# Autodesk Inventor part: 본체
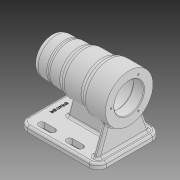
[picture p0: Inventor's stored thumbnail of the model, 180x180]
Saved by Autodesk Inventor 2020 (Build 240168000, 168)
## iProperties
Created: 2021-10
Part Number: 본체
Material: 일반
Document SubType Name: Modeling
Designer: user
Density: 1 g/cm^3
Appearance: 기본값
Author: user
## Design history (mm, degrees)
sketch "스케치1"
  geometry: L1 (56, 4)-(56, 17); L2 (56, 17)-(24, 17); L3 (24, 17)-(24, 13); L4 (24, 13)-(-10, 13); L5 (-10, 13)-(-10, 10); L6 (-10, 10)-(-32, 10); L7 (-32, 10)-(-32, 9); L8 (-32, 9)-(-56, 9); L9 (-56, 9)-(-56, -17); L10 (41, 4)-(56, 4); L11 (41, 4)-(41, 4); L12 (38, 7)-(-10, 7); L13 (-13, 4)-(-24.7, 4); L14 (-42.7, 0.5)-(-25, 0.5); L15 (-46.7, -1)-(-43, -1); L16 (-50, -17)-(-50, -9.5); L17 (-47, -6.5)-(-47, -6.5); L18 (-47, -1.3)-(-47, -6.5); L19 (-43, -1)-(-43, 0.2); L20 (-25, 0.5)-(-25, 3.7); L21 (-13, 4)-(-13, 4); L22 (-56, -17)-(41, -17); L23 (41, -17)-(41, 4); A1 r 3 centre (38, 4) between (41, 4) and (38, 7); A2 r 3 centre (-10, 4) between (-10, 7) and (-13, 4); A3 r 0.3 centre (-46.7, -1.3) between (-46.7, -1) and (-47, -1.3); A4 r 0.3 centre (-42.7, 0.2) between (-42.7, 0.5) and (-43, 0.2); A5 r 0.3 centre (-24.7, 3.7) between (-24.7, 4) and (-25, 3.7); A6 r 3 centre (-47, -9.5) between (-47, -6.5) and (-50, -9.5); 11 further points
  constraints: 46 end point, 14 point on line, 12 point on circle, 12 tangent, 10 perpendicular, 6 centre point, 2 equal radius, 2 horizontal, 2 parallel, 1 vertical
  dimensions: "d34" = 34 vertical distance of L22.end L1.end; "d36" = 97 distance of L22.end L9.end; "d37" = 17 distance from line of point (0, 0) L22; "d38" = 41 distance from line of point (0, 0) L23; "d39" = 112 distance between parallel lines of L1 L9; "d40" = 9 distance from line of point (0, 0) L8; "d42" = 50 distance from line of point (0, 0) L16; "d43" = 13.5 distance from line of L12 point (-50, -6.5); "d44" = 3 distance of point (-50, -6.5) L17.end; "d45" = 5.5 distance of point (-47, -1) L17.end; "d46" = 4 distance of point (-47, -1) L15.end; "d47" = 22 distance of L5.end L6.end; "d48" = 34 distance of L3.end L4.end; "d49" = 54 distance of point (41, 7) point (-13, 7); "d50" = 18 distance of point (-43, 0.5) L14.end; "d51" = 7 distance from line of L12 point (0, 0); "d52" = 13 distance from line of point (0, 0) L4; "d53" = 0.5 distance from line of point (0, 0) L14; "d54" = 47 distance from line of point (0, 0) L18; "d55" = 6.5 distance from line of point (0, 0) L17; "d58" = 4 distance from line of point (0, 0) L10; "d59" = 32 distance from line of point (0, 0) L7; "d60" = 1 distance from line of point (0, 0) L15; "d62" = 3 distance from line of L10 point (41, 7); "d63" = 3.5 distance from line of L14 point (-25, 4); "d64" = 10.5 distance from line of L22 point (-50, -6.5) (derived); "d137" = 3 radius of A1; "d138" = 3 radius of A2 (derived); "d139" = 0.3 radius of A3; "d143" = 3 radius of A6; "d145" = 24 horizontal distance of L8.end L6.end (derived); "d146" = 46 horizontal distance of L4.end L8.end (derived); "d147" = 80 horizontal distance of L2.end L8.end (derived); "d149" = 27 distance between parallel lines of L22 L6; "d150" = 26 distance of L9.end L8.end
revolve "회전1" sketch "스케치1" stored, may be unused: angle "d65" = 360 deg
node "작업 평면2"
  node "작업 평면1"
sketch "스케치2"
  geometry: L1 (-56, -45)-(56, -45); L2 (56, -45)-(56, 45); L3 (56, 45)-(-56, 45); L4 (-56, 45)-(-56, -45); 1 further point
  constraints: 8 end point, 2 parallel, 1 horizontal, 1 perpendicular
  dimensions: "d68" = 112 distance of L3.end L2.end; "d69" = 90 distance of L2.end L1.end; "d70" = 56 distance from line of point (0, 0) L4; "d71" = 45 distance from line of point (0, 0) L1
extrude "돌출1" join sketch "스케치2" distance "d72" = 8; taper "d73" = 0 deg
sketch "스케치3"
  geometry: L1 (56, 45)-(-56, 45) reference; L2 (-56, -45)-(56, -45) reference; L3 (56, -45)-(56, 45) reference; L4 (-29, 4)-(40, 4); L5 (40, 4)-(40, -4); L6 (40, -4)-(-29, -4); L7 (-29, -4)-(-29, 4); 1 further point
  constraints: 8 end point, 2 parallel, 1 horizontal, 1 perpendicular
  dimensions: "d79" = 69 distance of L5.end L6.end; "d80" = 8 distance of L4.end L5.end; "d83" = 4 distance from line of point (0, 0) L4; "d87" = 16 distance between parallel lines of L3 L5
extrude "돌출2" join sketch "스케치3" stored distance "d85" = 8; taper "d86" = 0 deg
sketch "스케치4"
  geometry: L1 (-19.409, 37.342)-(-33, 0); L2 (-41, 0)-(49, 0) reference; L3 (27.409, 37.342)-(39.635, 3.751); L4 (39.635, 3.751)-(41, 0); A1 r 34 centre (4, 62) between (-19.409, 37.342) and (27.409, 37.342) reference; 1 further point
  constraints: 6 end point, 3 point on line, 2 point on circle
  dimensions: "d88" = 8 distance of L2.start L1.end; "d89" = 70 deg angle of L2 L1; "d90" = 8 distance of L2.end L4.end; "d91" = 70 deg angle of L2 L3
extrude "돌출3" join sketch "스케치4" distance "d92" = 8; taper "d93" = 0 deg
feature "면 기울기1" dims angle "d95" = 15 deg
sketch "스케치6"
  geometry: L1 (0, 0)-(-26, 0); L2 (0, 0)-(13, 22.517); L3 (0, 0)-(26, 0); C1 r 26 at (0, 0); C2 r 34 at (0, 0) reference; A1 r 26 centre (0, 0) between (13, 22.517) and (-26, 0) reference; 2 further points
  constraints: 6 end point, 2 coincident, 2 horizontal, 2 point on circle, 1 centre point, 1 concentric, 1 equal length
  dimensions: "d103" = 52 diameter of C1; "d104" = 60 deg angle of L3 L2
hole "구멍1" sketch "스케치6" at (13, 22.517) diameter "d96" = 2.459; stored, may be unused: countersink angle "d100" = 90 deg, drill point angle "d102" = 118 deg; dims "d97" = 8, "d98" = 4, "d99" = 2, "d101" = 11
fillet "모깎기1" dims "d108" = 12
sketch "스케치7"
  geometry: L1 (19, -33)-(4, -33); L2 (19, -28.5)-(4, -28.5); L3 (4, -37.5)-(19, -37.5); L4 (-21, -33)-(-36, -33); L5 (-21, -28.5)-(-36, -28.5); L6 (-36, -37.5)-(-21, -37.5); L7 (-56, 33)-(-56, -33) reference; A1 r 4.5 centre (19, -33) between (19, -37.5) and (19, -28.5); A2 r 4.5 centre (4, -33) between (4, -28.5) and (4, -37.5); A3 r 4.5 centre (-21, -33) between (-21, -37.5) and (-21, -28.5); A4 r 4.5 centre (-36, -33) between (-36, -28.5) and (-36, -37.5); 3 further points
  constraints: 16 end point, 8 point on circle, 8 tangent, 4 centre point, 3 parallel, 2 midpoint, 1 horizontal alignment
  dimensions: "d113" = 7.5 distance of point (11.5, -33) L1.end; "d114" = 9 diameter of A2; "d115" = 7.5 distance of point (-28.5, -33) L4.end; "d116" = 9 diameter of A4; "d117" = 20 distance from line of L4.end L7; "d118" = 25 distance of L1.end L4.start; "d119" = 33 vertical distance of L4.end point (0, 0); "d120" = 33 vertical distance of point (11.5, -33) point (0, 0)
extrude "돌출4" cut sketch "스케치7" stored distance "d121" = 8; taper "d122" = 0 deg
fillet "모깎기2" dims "d123" = 3
fillet "모깎기3" dims "d124" = 3
fillet "모깎기7" dims "d128" = 8
fillet "모깎기9" dims "d130" = 8
fillet "모깎기10" dims "d131" = 3
chamfer "모따기1" distance "d132" = 1; stored, may be unused: second distance "d133" = 2, angle "d134" = 45 deg
sketch "스케치8"
  geometry: L1 (-56, 33)-(-56, -33) reference; 2 further points
  constraints: 1 horizontal alignment, 1 other
  dimensions: "d140" = 12 distance from line of L1 point (-44, 0)
extrude "돌출5" join sketch "스케치8" distance "d141" = 0.5; taper "d142" = 0 deg
fillet "모깎기13" dims "d144" = 3
node "솔리드1"
pattern_circular "원형 패턴1" dims angle "d106" = 360 deg
mirror "미러1"
feature "A9D066F2-1C7D-4E18-AEED-F7BC21143FA4" dims "d96" = 2.459, "d97" = 8, "d98" = 4, "d99" = 2, "d100" = 90 deg, "d101" = 11, "d102" = 118 deg
other parameters: "d66" = -17, "sa_0" = 4
